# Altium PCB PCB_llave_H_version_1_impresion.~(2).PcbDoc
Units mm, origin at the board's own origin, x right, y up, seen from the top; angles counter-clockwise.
Board outline 85.85 x 71.63 mm, 2 copper layers (Top Layer, Bottom Layer); 116 components, 33 nets, 344 pads, 10 vias.
Unrouted connection lines stored in the file: 18.
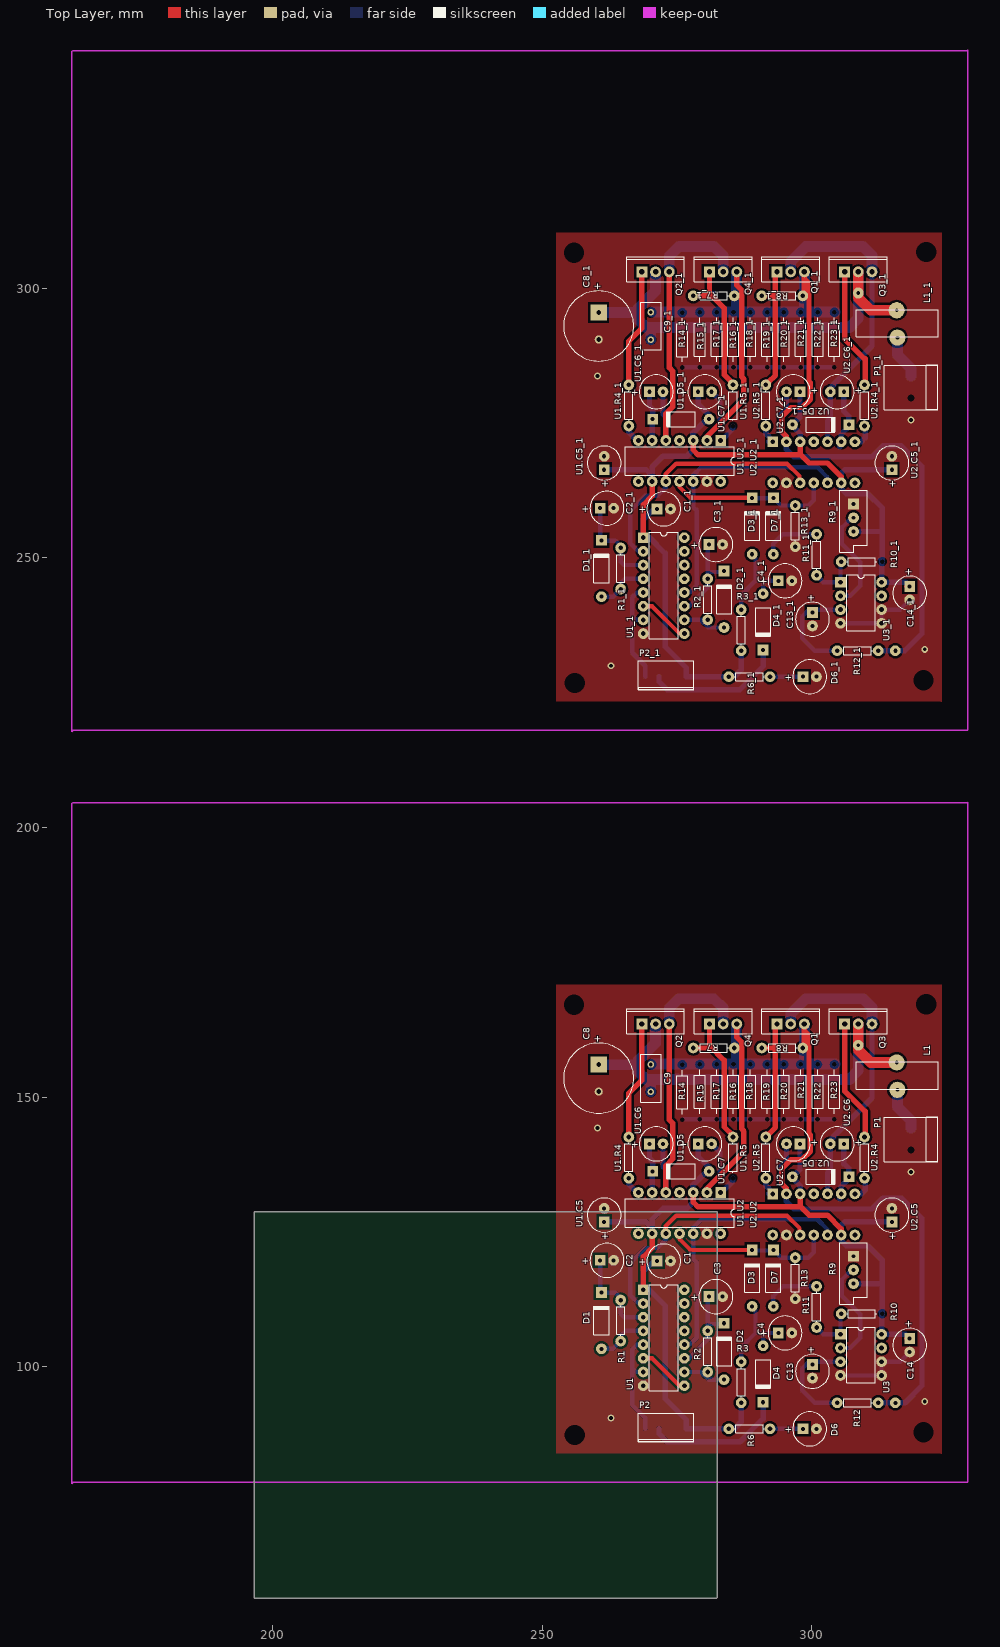
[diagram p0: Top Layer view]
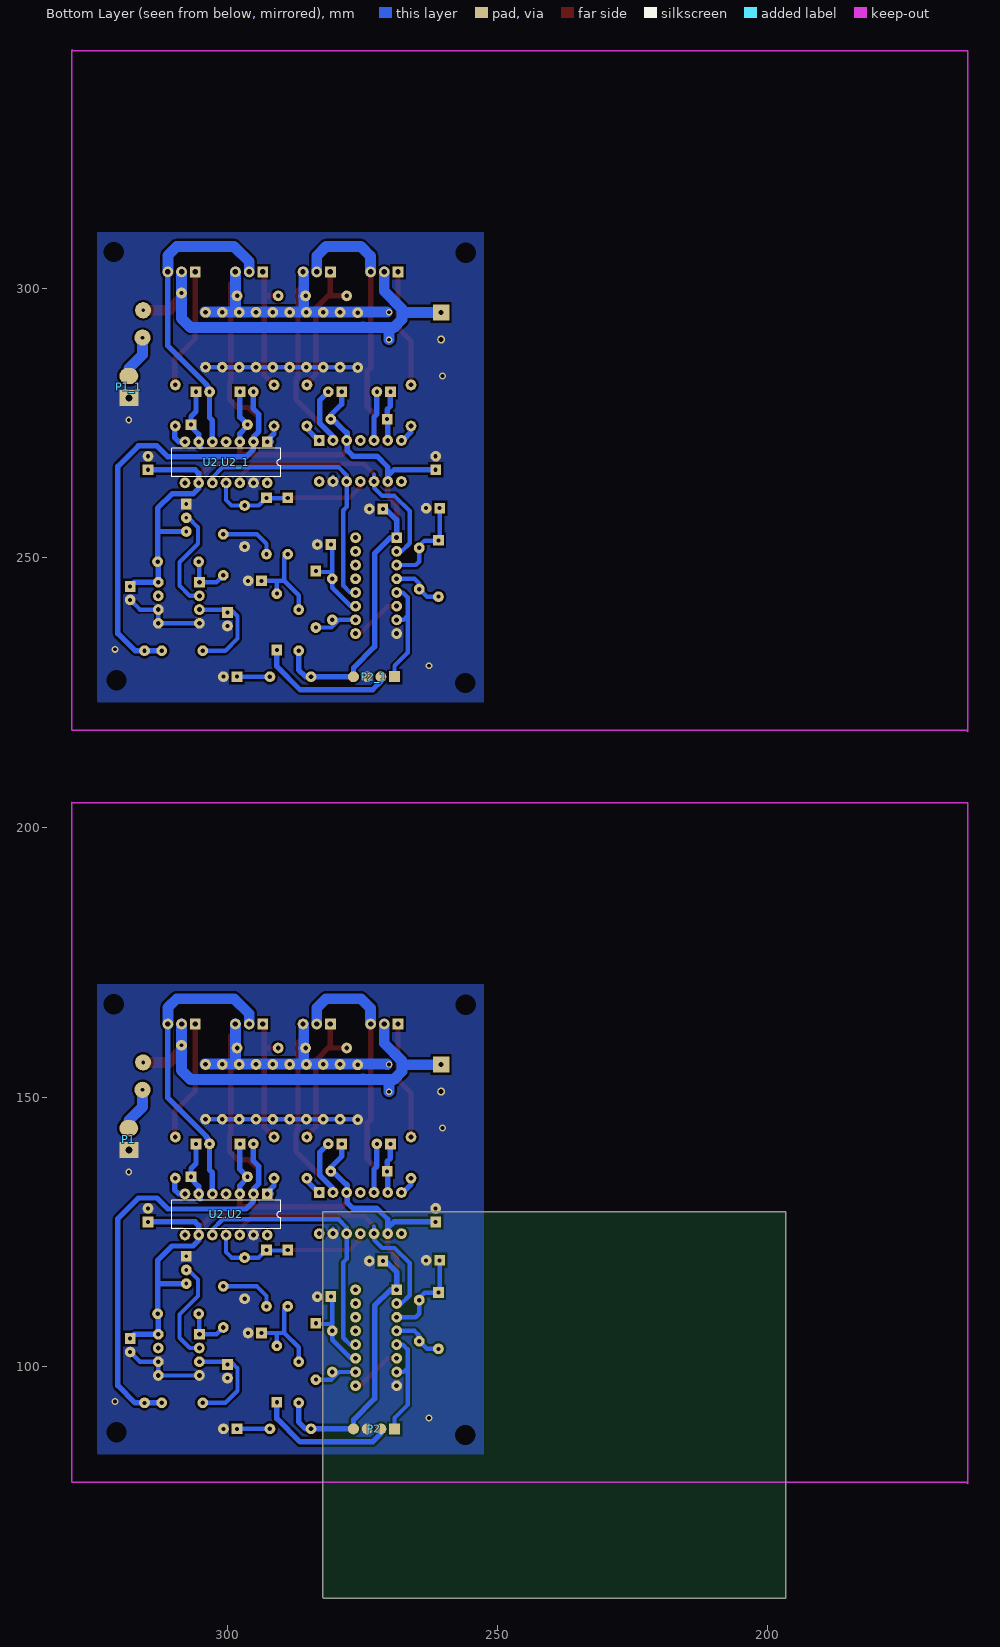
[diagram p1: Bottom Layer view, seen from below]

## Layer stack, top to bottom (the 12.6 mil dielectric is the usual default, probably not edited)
Top Layer: signal copper 0.0356
Dielectric: dielectric 0.32, FR-4, Dk 4.8
Bottom Layer: signal copper 0.0356

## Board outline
196.596,128.778 282.448,128.778 282.448,57.277 282.321,57.15 196.596,57.15

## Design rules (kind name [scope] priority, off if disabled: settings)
Clearance [All] p1: gap=0.4
ComponentClearance [All] p1: gap=0.254 collisioncheckmode=2 verticalgap=0.254
PlaneConnect [All] p1: planeconnectstyle=Direct reliefexpansion=0.508 reliefentries=4 reliefconductorwidth=0.254 reliefairgap=0.254
PolygonConnect [All] p1: connectstyle=Direct reliefconductorwidth=0.254 reliefentries=4 polygonreliefangle="90 Angle"
RoomDefinition U2_1 [InComponentClass('U2')] p1: confinementstyle=ConfineIn formatcopy=TRUE lockcomponents=FALSE outline 311.404,303.657 311.404,256.032 279.527,256.032 279.527,303.657
RoomDefinition U1_1 [InComponentClass('U1')] p2: confinementstyle=ConfineIn formatcopy=TRUE lockcomponents=FALSE outline 255.397,298.069 255.397,257.556 287.02,257.556 287.02,298.069
RoomDefinition U_Puente_H_1 [InComponentClass('U_Puente_H')] p3: confinementstyle=ConfineIn formatcopy=TRUE lockcomponents=FALSE outline 253.746,309.245 324.104,309.245 324.104,274.447 253.746,274.447
RoomDefinition U_INITShutdown_1 [InComponentClass('U_INITShutdown')] p4: confinementstyle=ConfineIn formatcopy=TRUE lockcomponents=FALSE outline 282.956,225.298 298.704,225.298 298.704,263.144 282.956,263.144
RoomDefinition U_Shutdown_1 [InComponentClass('U_Shutdown')] p5: confinementstyle=ConfineOut formatcopy=TRUE lockcomponents=FALSE outline 285.115,227.838 285.115,229.235 288.417,229.235 288.417,227.838
RoomDefinition Llave_H_esquema_1 [InComponentClass('Llave_H_esquema')] p6: confinementstyle=ConfineIn formatcopy=TRUE lockcomponents=FALSE outline 324.104,223.393 324.104,309.245 252.603,309.245 252.603,223.393
RoomDefinition U_4049_1 [InComponentClass('U_4049')] p7: confinementstyle=ConfineIn formatcopy=TRUE lockcomponents=FALSE outline 287.528,233.172 287.528,267.208 257.048,267.208 257.048,233.172
RoomDefinition U2 [InComponentClass('U2')] p8: confinementstyle=ConfineIn formatcopy=TRUE lockcomponents=FALSE outline 311.404,164.211 311.404,116.586 279.527,116.586 279.527,164.211
RoomDefinition U1 [InComponentClass('U1')] p9: confinementstyle=ConfineIn formatcopy=TRUE lockcomponents=FALSE outline 255.397,158.623 255.397,118.11 287.02,118.11 287.02,158.623
RoomDefinition U_Puente_H [InComponentClass('U_Puente_H')] p10: confinementstyle=ConfineIn formatcopy=TRUE lockcomponents=FALSE outline 253.746,169.799 324.104,169.799 324.104,135.001 253.746,135.001
RoomDefinition U_INITShutdown [InComponentClass('U_INITShutdown')] p11: confinementstyle=ConfineIn formatcopy=TRUE lockcomponents=FALSE outline 282.956,85.852 298.704,85.852 298.704,123.698 282.956,123.698
RoomDefinition U_Shutdown [InComponentClass('U_Shutdown')] p12: confinementstyle=ConfineOut formatcopy=TRUE lockcomponents=FALSE outline 285.115,88.392 285.115,89.789 288.417,89.789 288.417,88.392
RoomDefinition Llave_H_esquema [InComponentClass('Llave_H_esquema')] p13: confinementstyle=ConfineIn formatcopy=TRUE lockcomponents=FALSE outline 324.104,83.947 324.104,169.799 252.603,169.799 252.603,83.947
RoomDefinition U_4049 [InComponentClass('U_4049')] p14: confinementstyle=ConfineIn formatcopy=TRUE lockcomponents=FALSE outline 287.528,93.726 287.528,127.762 257.048,127.762 257.048,93.726
RoutingVias [All] p1: holewidth=0.711 width=1.27 viastyle="Through Hole" minholewidth=0.711 minwidth=1.27 maxholewidth=0.711 maxwidth=1.27
SolderMaskExpansion [All] p1: expansion=0.102
TestPointUsage [All] p1: valid=0 allowmultiple=FALSE
Testpoint [All] p1: side=15 testpointundercomponent=TRUE minsize=1.016 maxsize=2.54 preferedsize=1.524 minholesize=0 maxholesize=1.016 preferedholesize=0.813 testpointgrid=0.025 style=1023 order=0-112345678
Width [All] p1: maxlimit=3 minlimit=0.8 preferedwidth=1
17 further rules are at their usual default settings.

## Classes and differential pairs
component class U2: D5 U2.C5 U2.C6 U2.C7 U2.D5 U2.R4 U2.R5 U2.U2 U_2.D5 U_2_C5 U_2_C6 U_2_C7 U_2_R4 U_2_R5 U_2_U2
component class U1: U1.C5 U1.C6 U1.C7 U1.D5 U1.R4 U1.R5 U1.U2 U_1_C5 U_1_C6 U_1_C7 U_1_D5 U_1_R4 U_1_R5 U_1_U2
component class U_INITShutdown: C4 D3 D4 R3
channel class IR2110: U1 U2
component class U_Shutdown: C13 C14 D7 R9 R10 R11 R12 R13 R14 R15 R16 R17 R18 R19 R20 R21 R22 R23 U3
component class U_Puente_H: C8 C9 L1 Q1 Q2 Q3 Q4 R7 R8
component class U_4049: C1 C2 C3 D1 D2 R1 R2 U1
component class Llave_H_esquema: D6 P1 P2 R6

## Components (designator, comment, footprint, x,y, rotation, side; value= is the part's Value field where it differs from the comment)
C1 "Cap Pol1 0.1u" CAPPR2.5-6.3X5 272.542,119.634 r0 top
C1_1 "Cap Pol1 0.1u" CAPPR2.5-6.3X5 272.542,259.08 r0 top (schematic designator C1)
C2 "Cap Pol1" CAPPR2.5-6.3X5 262.001,119.761 r0 top
C2_1 "Cap Pol1" CAPPR2.5-6.3X5 262.001,259.207 r0 top (schematic designator C2)
C3 "Cap Pol1" CAPPR2.5-6.3X5 282.194,113.03 r0 top
C3_1 "Cap Pol1" CAPPR2.5-6.3X5 282.194,252.476 r0 top (schematic designator C3)
C4 "Cap Pol1 4.7u" CAPPR2.5-6.3X5 295.021,106.299 r0 top
C4_1 "Cap Pol1 4.7u" CAPPR2.5-6.3X5 295.021,245.745 r0 top (schematic designator C4)
C8 "Cap Pol1" CAPPR5-13X16 260.477,153.543 r270 top
C8_1 "Cap Pol1" CAPPR5-13X16 260.477,292.989 r270 top (schematic designator C8)
C9 "Cap" RAD-0.2 270.129,153.543 r270 top
C9_1 "Cap" RAD-0.2 270.129,292.989 r270 top (schematic designator C9)
C13 "Cap Pol1 4.7u" CAPPR2.5-6.3X5 300.101,99.187 r270 top
C13_1 "Cap Pol1 4.7u" CAPPR2.5-6.3X5 300.101,238.633 r270 top (schematic designator C13)
C14 "Cap Pol1 0.1u" CAPPR2.5-6.3X5 318.135,104.013 r270 top
C14_1 "Cap Pol1 0.1u" CAPPR2.5-6.3X5 318.135,243.459 r270 top (schematic designator C14)
D1 "Diode1" DO-204AL 260.985,108.585 r90 top
D1_1 "Diode1" DO-204AL 260.985,248.031 r90 top (schematic designator D1)
D2 "Diode1" DO-204AL 283.718,102.87 r90 top
D2_1 "Diode1" DO-204AL 283.718,242.316 r90 top (schematic designator D2)
D3 "Diode1" DO-204AL 288.925,116.459 r90 top
D3_1 "Diode1" DO-204AL 288.925,255.905 r90 top (schematic designator D3)
D4 "Diode1" DO-204AL 290.957,98.679 r270 top
D4_1 "Diode1" DO-204AL 290.957,238.125 r270 top (schematic designator D4)
D6 "LED0" CAPPR2.5-6.3X5 299.593,88.519 r0 top
D6_1 "LED0" CAPPR2.5-6.3X5 299.593,227.965 r0 top (schematic designator D6)
D7 "Diode1" DO-204AL 292.862,116.459 r90 top
D7_1 "Diode1" DO-204AL 292.862,255.905 r90 top (schematic designator D7)
L1 "Inductor" bobina_Choque 313.309,151.511 r0 top
L1_1 "Inductor" bobina_Choque 313.309,290.957 r0 top (schematic designator L1)
P1 "Header 2" pwheader1x2 318.389,142.367 r90 top
P1_1 "Header 2" pwheader1x2 318.389,281.813 r90 top (schematic designator P1)
P2 "Header 4" HDR1X5 276.733,80.899 r0 top
P2_1 "Header 4" HDR1X5 276.733,220.345 r0 top (schematic designator P2)
Q1 "IRF3205" TO-220AB 308.61,163.576 r0 top
Q1_1 "IRF3205" TO-220AB 308.61,303.022 r0 top (schematic designator Q1)
Q2 "IRF3205" TO-220AB 271.018,163.576 r0 top
Q2_1 "IRF3205" TO-220AB 271.018,303.022 r0 top (schematic designator Q2)
Q3 "IRF3205" TO-220AB 296.079,163.576 r0 top
Q3_1 "IRF3205" TO-220AB 296.079,303.022 r0 top (schematic designator Q3)
Q4 "IRF3205" TO-220AB 283.549,163.576 r0 top
Q4_1 "IRF3205" TO-220AB 283.549,303.022 r0 top (schematic designator Q4)
R1 "18k" AXIAL-0.3#1 264.541,108.585 r270 top
R1_1 "18k" AXIAL-0.3#1 264.541,248.031 r270 top (schematic designator R1)
R2 "18k" AXIAL-0.3#1 280.67,102.87 r90 top
R2_1 "18k" AXIAL-0.3#1 280.67,242.316 r90 top (schematic designator R2)
R3 "4.7k" AXIAL-0.3#1 286.893,97.155 r270 top
R3_1 "4.7k" AXIAL-0.3#1 286.893,236.601 r270 top (schematic designator R3)
R6 "1.2k" AXIAL-0.3#1 288.417,88.519 r180 top
R6_1 "1.2k" AXIAL-0.3#1 288.417,227.965 r180 top (schematic designator R6)
R7 "6.8" AXIAL-0.3#1 281.813,159.131 r180 top
R7_1 "6.8" AXIAL-0.3#1 281.813,298.577 r180 top (schematic designator R7)
R8 "6.8" AXIAL-0.3#2 294.513,159.131 r180 top
R8_1 "6.8" AXIAL-0.3#2 294.513,298.577 r180 top (schematic designator R8)
R9 "RPot" VR5 307.721,117.983 r270 top
R9_1 "RPot" VR5 307.721,257.429 r270 top (schematic designator R9)
R10 "3.3k" AXIAL-0.3#3 309.245,109.855 r0 top
R10_1 "3.3k" AXIAL-0.3#3 309.245,249.301 r0 top (schematic designator R10)
R11 "470" AXIAL-0.3#1 300.863,111.125 r90 top
R11_1 "470" AXIAL-0.3#1 300.863,250.571 r90 top (schematic designator R11)
R12 "6.8" AXIAL-0.3#1 308.483,93.345 r180 top locked
R12_1 "6.8" AXIAL-0.3#1 308.483,232.791 r180 top locked (schematic designator R12)
R13 "10k" AXIAL-0.3#1 296.926,116.459 r90 top
R13_1 "10k" AXIAL-0.3#1 296.926,255.905 r90 top (schematic designator R13)
R14 "Res2" AXIAL-0.4#1 275.971,150.936 r90 top
R14_1 "Res2" AXIAL-0.4#1 275.971,290.382 r90 top (schematic designator R14)
R15 "Res2" AXIAL-0.4#1 279.227,151.003 r90 top
R15_1 "Res2" AXIAL-0.4#1 279.227,290.449 r90 top (schematic designator R15)
R16 "Res2" AXIAL-0.4#1 282.344,151.003 r90 top
R16_1 "Res2" AXIAL-0.4#1 282.344,290.449 r90 top (schematic designator R16)
R17 "Res2" AXIAL-0.4#1 285.462,151.003 r90 top
R17_1 "Res2" AXIAL-0.4#1 285.462,290.449 r90 top (schematic designator R17)
R18 "Res2" AXIAL-0.4#1 288.579,151.003 r90 top
R18_1 "Res2" AXIAL-0.4#1 288.579,290.449 r90 top (schematic designator R18)
R19 "Res2" AXIAL-0.4#1 291.696,151.003 r90 top
R19_1 "Res2" AXIAL-0.4#1 291.696,290.449 r90 top (schematic designator R19)
R20 "Res2" AXIAL-0.4#2 294.813,151.003 r90 top
R20_1 "Res2" AXIAL-0.4#2 294.813,290.449 r90 top (schematic designator R20)
R21 "Res2" AXIAL-0.4#2 297.931,151.003 r90 top
R21_1 "Res2" AXIAL-0.4#2 297.931,290.449 r90 top (schematic designator R21)
R22 "Res2" AXIAL-0.4#2 301.048,151.003 r90 top
R22_1 "Res2" AXIAL-0.4#2 301.048,290.449 r90 top (schematic designator R22)
R23 "Res2" AXIAL-0.4#2 304.165,151.003 r90 top
R23_1 "Res2" AXIAL-0.4#2 304.165,290.449 r90 top (schematic designator R23)
U1 "MC54HC4049J" 620-09 272.542,105.41 r270 top
U1.C5 "Cap Pol1 4.7u" CAPPR2.5-6.3X5 261.493,128.143 r90 top (schematic designator C5)
U1.C5_1 "Cap Pol1 4.7u" CAPPR2.5-6.3X5 261.493,267.589 r90 top (schematic designator C5)
U1.C6 "Cap Pol1" CAPPR2.5-6.3X5 271.145,141.351 r0 top (schematic designator C6)
U1.C6_1 "Cap Pol1" CAPPR2.5-6.3X5 271.145,280.797 r0 top (schematic designator C6)
U1.C7 "Cap Pol1" CAPPR2.5-6.3X5 280.162,141.351 r0 top (schematic designator C7)
U1.C7_1 "Cap Pol1" CAPPR2.5-6.3X5 280.162,280.797 r0 top (schematic designator C7)
U1.D5 "Diode" DO-204AL 275.717,136.271 r180 top (schematic designator D5)
U1.D5_1 "Diode" DO-204AL 275.717,275.717 r180 top (schematic designator D5)
U1.R4 "10" AXIAL-0.3#1 266.065,138.811 r90 top (schematic designator R4)
U1.R4_1 "10" AXIAL-0.3#1 266.065,278.257 r90 top (schematic designator R4)
U1.R5 "10" AXIAL-0.3#4 285.369,138.811 r90 top (schematic designator R5)
U1.R5_1 "10" AXIAL-0.3#4 285.369,278.257 r90 top (schematic designator R5)
U1.U2 "IR2110" PDIP14 275.463,128.524 r180 top (schematic designator U2)
U1.U2_1 "IR2110" PDIP14 275.463,267.97 r180 top (schematic designator U2)
U1_1 "MC54HC4049J" 620-09 272.542,244.856 r270 top (schematic designator U1)
U2.C5 "Cap Pol1 4.7u" CAPPR2.5-6.3X5 314.833,128.143 r90 top (schematic designator C5)
U2.C5_1 "Cap Pol1 4.7u" CAPPR2.5-6.3X5 314.833,267.589 r90 top (schematic designator C5)
U2.C6 "Cap Pol1" CAPPR2.5-6.3X5 304.673,141.351 r180 top (schematic designator C6)
U2.C6_1 "Cap Pol1" CAPPR2.5-6.3X5 304.673,280.797 r180 top (schematic designator C6)
U2.C7 "Cap Pol1" CAPPR2.5-6.3X5 296.545,141.351 r180 top (schematic designator C7)
U2.C7_1 "Cap Pol1" CAPPR2.5-6.3X5 296.545,280.797 r180 top (schematic designator C7)
U2.D5 "Diode" DO-204AL 301.625,135.255 r0 top (schematic designator D5)
U2.D5_1 "Diode" DO-204AL 301.625,274.701 r0 top (schematic designator D5)
U2.R4 "10" AXIAL-0.3#1 309.753,138.811 r90 top (schematic designator R4)
U2.R4_1 "10" AXIAL-0.3#1 309.753,278.257 r90 top (schematic designator R4)
U2.R5 "10" AXIAL-0.3#1 291.465,138.811 r90 top (schematic designator R5)
U2.R5_1 "10" AXIAL-0.3#1 291.465,278.257 r90 top (schematic designator R5)
U2.U2 "IR2110" PDIP14 300.355,128.27 r0 bottom (schematic designator U2)
U2.U2_1 "IR2110" PDIP14 300.355,267.716 r0 bottom (schematic designator U2)
U3 "LM393N" 626-05 309.118,102.235 r270 top
U3_1 "LM393N" 626-05 309.118,241.681 r270 top (schematic designator U3)

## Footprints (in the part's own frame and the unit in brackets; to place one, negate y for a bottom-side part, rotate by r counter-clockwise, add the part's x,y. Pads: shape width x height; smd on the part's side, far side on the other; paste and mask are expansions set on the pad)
620-09 [mm] "DIP; 16 Leads; Row Spacing 7.62 mm; Pitch 2.54 mm"
  rect 2x2 hole 0.9: 1(-8.89,-3.81)
  round 2 hole 0.9: 2(-6.35,-3.81) 3(-3.81,-3.81) 4(-1.27,-3.81) 5(1.27,-3.81) 6(3.81,-3.81) 7(6.35,-3.81) 8(8.89,-3.81) 9(8.89,3.81) 10(6.35,3.81) 11(3.81,3.81) 12(1.27,3.81) 13(-1.27,3.81) 14(-3.81,3.81) 15(-6.35,3.81) 16(-8.89,3.81)
  silkscreen extent -9.85,-2.65 9.85,2.65
626-05 [mm] "DIP; 8 Leads; Row Spacing 7.62 mm; Pitch 2.54 mm"
  rect 2x2 hole 0.9: 1(-3.81,-3.81)
  round 2 hole 0.9: 2(-1.27,-3.81) 3(1.27,-3.81) 4(3.81,-3.81) 5(3.81,3.81) 6(1.27,3.81) 7(-1.27,3.81) 8(-3.81,3.81)
  silkscreen extent -5.15,-2.65 5.15,2.65
AXIAL-0.3#1 [mm] "Resistor; 2 Leads"
  round 2 hole 0.85: 1(-3.81,0) 2(3.81,0)
  silkscreen extent -2.77,-0.76 2.77,0.76
AXIAL-0.3#2 [mm] "Resistor; 2 Leads"
  round 2 hole 0.85 paste+0 mask+0.102: 1(-3.81,0)
  round 2 hole 0.85: 2(3.81,0)
  silkscreen extent -2.77,-0.76 2.77,0.76
AXIAL-0.3#3 [mm] "Resistor; 2 Leads"
  round 2 hole 0.85: 1(-3.81,0)
  round 0 / inner round 0 / far side round 2 hole 0.85: 2(3.81,0)
  silkscreen extent -2.77,-0.76 2.77,0.76
AXIAL-0.3#4 [mm] "Resistor; 2 Leads"
  round 0 / inner round 0 / far side round 2 hole 0.85: 1(-3.81,0)
  round 2 hole 0.85: 2(3.81,0)
  silkscreen extent -2.77,-0.76 2.77,0.76
AXIAL-0.4#1 [mm] "Resistor; 2 Leads"
  round 0 / inner round 0 / far side round 2 hole 0.85: 1(-5.08,0) 2(5.08,0)
  silkscreen extent -4.06,-1.02 4.06,1.02
AXIAL-0.4#2 [mm] "Resistor; 2 Leads"
  round 0 / inner round 0 / far side round 2 hole 0.85: 1(-5.08,0)
  round 0 / inner round 0 / far side round 2 hole 0.85 unplated: 2(5.08,0)
  silkscreen extent -4.06,-1.02 4.06,1.02
bobina_Choque [mm]
  round 3 hole 0.7: 1(2.54,-0.127) 2(2.413,4.953)
  silkscreen extent -5.08,0 10.16,5.08
CAPPR2.5-6.3X5 [mm] "Capacitor, Electrolytic, Radial; Body 6.3 x 5 mm (Dia.xH typ); Pin Spacing 2.5 mm (typ)"
  rect 2x2 hole 0.75: 1(-1.25,0)
  round 2 hole 0.75: 2(1.25,0)
  silkscreen extent -3.15,-3.15 3.15,3.15
CAPPR5-13X16 [mm] "Capacitor, Electrolytic, Radial; Body 13 x 16 mm (Dia.xH typ); Pin Spacing 5 mm (typ)"
  rect 3x3 hole 0.9: 1(-2.5,0)
  round 1.5 hole 0.9: 2(2.5,0)
  silkscreen extent -6.5,-6.5 6.5,6.5
DO-204AL [mm] "Diode, Axial; Body 5.2 x 2.7 mm (LxDia. max), Lead Dia. 0.86 mm (max)"
  round 2 hole 0.75: 1(-5.23,0)
  rect 2x2 hole 0.75: 2(5.23,0)
  silkscreen extent -2.65,-1.4 2.75,1.4
HDR1X5 [mil]
  rect 80x80 smd far side: 1(-300,300)
  round 80 smd far side: 2(-200,300) 3(-100,300) 4(0,300)
  silkscreen extent -350,205 55,415
PDIP14 [mm] "DIP; 14 Leads; Row Spacing 7.62 mm; Pitch 2.54 mm"
  rect 2x2 hole 0.9: 1(-7.62,-3.81)
  round 2 hole 0.9: 2(-5.08,-3.81) 3(-2.54,-3.81) 4(0,-3.81) 5(2.54,-3.81) 6(5.08,-3.81) 7(7.62,-3.81) 8(7.62,3.81) 9(5.08,3.81) 10(2.54,3.81) 11(0,3.81) 12(-2.54,3.81) 13(-5.08,3.81) 14(-7.62,3.81)
  silkscreen extent -10.1,-2.65 10.1,2.65
pwheader1x2 [mm]
  round 0 / inner round 0 / far side rect 3x3.5 hole 1.3: 1(-2.159,0)
  oval 3x3.5 smd far side: 2(1.905,0)
  silkscreen extent -4.32,-4.95 3.94,4.95
RAD-0.2 [mm] "Jumper Wire; 2 Leads"
  round 1.2 hole 0.7: 1(-2.54,0) 2(2.54,0)
  silkscreen extent -4.44,-1.91 4.44,1.91
TO-220AB [mm] "TO, Thru-Hole, Vertical, Heatsink Mounted; 3 In-Line Leads; Pitch 2.54 mm"
  rect 2x2 hole 1: 1(-2.54,0)
  round 2 hole 1: 2(0,0) 3(2.54,0)
  silkscreen extent -5.35,-1.85 5.35,2.85
VR5 [mm] "Potentiometer; 3 Leads"
  rect 2x2 hole 0.7: 1(-2.54,0)
  round 2 hole 0.7: 2(2.54,0) 3(0,0)
  silkscreen extent -5.08,-2.54 6.35,2.54

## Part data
C1 C1_1 C4 C4_1 C14 C14_1 U1.C5 U1.C5_1 U2.C5 U2.C5_1: library part "Cap Pol1", "Polarized Capacitor (Radial)"
C2 C2_1 C3 C3_1 C8 C8_1 U1.C6 U1.C6_1 U1.C7 U1.C7_1 U2.C6 U2.C6_1 U2.C7 U2.C7_1: "Polarized Capacitor (Radial)"
C9 C9_1: "Capacitor"
C13 C13_1: library part "Cap Pol1", "Polarized 16V"
D1 D1_1 D2 D2_1: library part Diode, "1N4148"
D3 D3_1 D4 D4_1 D7 D7_1: library part Diode, "1n4148"
D6 D6_1: "Typical INFRARED GaAs LED"
P1 P1_1: "Header, 2-Pin"
P2 P2_1: "Header, 4-Pin"
Q1 Q1_1 Q2 Q2_1 Q3 Q3_1 Q4 Q4_1: "HEXFET Power MOSFET"
R1 R1_1 R2 R2_1 R3 R3_1 R6 R6_1 R7 R7_1 R8 R8_1 U1.R4 U1.R4_1 U1.R5 U1.R5_1 U2.R4 U2.R4_1 U2.R5 U2.R5_1: library part Res2, "Resistor"
R9 R9_1: "Potenciomentro multivuelta"
R10 R10_1 R11 R11_1 R12 R12_1 R13 R13_1: library part Res2, "metal film 1/2 W"
R14 R14_1 R15 R15_1 R16 R16_1 R17 R17_1 R18 R18_1 R19 R19_1 R20 R20_1 R21 R21_1 R22 R22_1 R23 R23_1: "metal film 1W"
U1 U1_1: "Hex Inverting Buffer/Logic-Level Down Converter"
U1.D5 U1.D5_1 U2.D5 U2.D5_1: "1N5819"
U1.U2 U1.U2_1 U2.U2 U2.U2_1: "High and Low Side Driver"
U3 U3_1: "Dual Comparator"

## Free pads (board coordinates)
  round 1.524 hole 3.75: 0(255.905,167.132) 0(255.905,306.578) 0(256.032,87.376) 0(256.032,226.822) 0(320.675,87.884) 0(320.675,227.33) 0(321.183,167.259) 0(321.183,306.705)
  round 2 hole 0.762: 1(315.468,93.345) 1(315.468,232.791)

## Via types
v1: diameter 1.27, hole 0.711, Top Layer to Bottom Layer, 8 vias
v2: diameter 2, hole 0.711, Top Layer to Bottom Layer, 2 vias

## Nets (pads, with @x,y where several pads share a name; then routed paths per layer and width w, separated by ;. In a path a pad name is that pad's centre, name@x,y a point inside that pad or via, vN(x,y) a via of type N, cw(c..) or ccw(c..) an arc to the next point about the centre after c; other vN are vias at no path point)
COMMON: C9.1 pad.1@315.468,93.345 Q3.3 Q4.3 R7.1 R8.1 R12.1 R14.2 R15.2 R16.2 R17.2 R18.2 R19.2 R20.2 R21.2 R22.2 R23.2 U1.C7.2 U1.U2.2 U2.C7.2 U2.U2.2 | length 217.5
  Top Layer w1: U1.U2.2 280.543,133.096 287.401,139.954 287.401,143.637 287.274,143.764 287.274,143.891 287.02,144.145 287.02,160.147 286.089,161.078 Q4.3 ; U2.U2.2 295.275,133.096 294.386,133.985 294.386,136.652 296.164,138.43 298.196,138.43 299.72,139.954 299.72,142.997 299.466,143.251 299.466,161.417 298.619,162.264 ; R8.1@298.619,159.131 Q3.3
  Bottom Layer w1: U1.U2.2 280.543,133.096 282.956,135.509 282.956,139.807 U1.C7.2 ; R7.1@286.004,159.064 286.089,159.149 Q4.3 ; U2.C7.2 295.295,138.196 294.279,137.18 294.279,133.98 295.275,132.984 295.275,130.683 296.672,129.286 311.15,129.286 313.182,131.318 316.611,131.318 320.421,127.508 320.421,96.52 317.246,93.345 R12.1
  Bottom Layer w2: C9.1@270.475,156.083 270.536,156.143 R23.2@304.292,156.143 ; R17.2@285.97,156.143 Q4.3@285.97,163.542 ; R7.1@285.97,159.131 R7.1@286.036,159.064 ; R21.2@298.619,156.143 Q3.3
GND: C1.2 C2.2 C3.2 C4.2 C8.2 C13.2 C14.2 D6.2 P1.1 P2.3 pad.0@255.905,167.132 pad.0@256.032,87.376 pad.0@320.675,87.884 pad.0@321.183,167.259 R9.1 R13.1 R14.1 R15.1 R16.1 R17.1 R18.1 R19.1 R20.1 R21.1 R22.1 R23.1 U1.8 U1.C5.2 U1.U2.13 U2.C5.2 U2.U2.13 U3.4 U3.5 U3.6 | length 45.2
  Top Layer w0.8: U3.5@312.888,98.425 312.908,98.445 U3.5 ; U3.6@312.908,100.945 U3.6
  Bottom Layer w0.8: R14.1@276.038,145.923 R23.1 ; U1.U2.13 U1.U2.13@280.543,125.603 ; U3.4 U3.5 ; U3.5@312.908,98.445 U3.6@312.908,100.945 ; U3.6 316.337,100.965 C14.2
  other v1: 262.763,90.551 320.929,93.599 318.389,136.144 260.223,144.272
HO1: Q2.1 U1.R4.2 | length 22
  Top Layer w1: U1.R4.2 266.065,150.749 268.478,153.162 Q2.1
HO2: Q1.1 U2.R4.2 | length 22
  Top Layer w1: Q1.1 306.07,151.13 309.88,147.32 ; U2.R4.2@309.88,143.256 309.88,147.447
IN_SD: D4.2 P2.2 | length 25.6
  Bottom Layer w1: P2.2 271.653,87.63 273.177,86.106 286.639,86.106 290.957,90.424 D4.2
LO1: Q4.1 R7.2 U1.R5.2 | length 26.4
  Top Layer w1: R7.2@277.749,159.131 281.409,159.131 281.421,159.142 ; Q4.1 281.009,159.554 283.718,156.845 283.718,144.526 285.369,142.875 U1.R5.2
LO2: Q3.1 R8.2 U2.R5.2 | length 24.5
  Top Layer w1: R8.2@290.322,158.877 R8.2@290.576,159.131 ; R8.2 293.243,159.131 ; U2.R5.2@291.465,143.129 291.973,143.129 293.243,144.399 293.243,163.28 Q3.1
MOTOR+: Q2.3 Q4.2 U1.C6.2 U1.U2.5 | length 58.6
  Top Layer w1: U1.U2.5 272.923,137.287 274.193,138.557 274.193,145.187 273.558,145.822 Q2.3
  Bottom Layer w1: U1.C6.2 272.395,137.18 272.923,136.652 U1.U2.5
  Bottom Layer w2: Q2.3 273.558,166.497 275.336,168.275 281.813,168.275 283.549,166.539 Q4.2
MOTOR-: Q1.3 Q3.2 U2.C6.2 U2.U2.5 | length 56.8
  Bottom Layer w1: U2.U2.5 302.895,136.017 303.423,136.545 303.423,142.006 304.023,142.606 304.023,142.733 311.15,149.86 Q1.3
  Bottom Layer w2: Q3.2 296.079,165.481 298.873,168.275 309.499,168.275 311.15,166.624 Q1.3
NetC2_1: C2.1 D1.2 R1.1 U1.3 | length 17.4
  Bottom Layer w0.8: C2.1 260.751,114.049 261.046,113.754 263.563,113.754 264.541,112.776 264.541,109.855 265.176,109.22 U1.3
NetC3_1: C3.1 D2.2 R2.2 U1.11 | length 17
  Bottom Layer w0.8: U1.11 277.241,101.6 280.67,105.029 280.67,112.756 C3.1 ; 280.67,107.95 283.568,107.95 D2.2
NetC4_1: C4.1 D3.1 D4.1 R3.1 | length 18.2
  Bottom Layer w0.8: R3.1 286.893,103.632 289.56,106.299 ; D3.1 289.56,110.594 289.56,106.299 ; D4.1 290.957,106.299 ; C4.1 289.56,106.299
NetC13_1: C13.1 R12.2 U3.3 | length 19.1
  Bottom Layer w0.8: R12.2 300.482,93.345 298.236,95.591 298.236,99.735 299.466,100.965 U3.3
NetD1_1: D1.1 R1.2 U1.4 | length 9.7
  Bottom Layer w0.8: D1.1 263.121,103.355 R1.2 264.541,105.791 265.43,106.68 U1.4
NetD2_1: D2.1 R2.1 U1.10 | length 8
  Bottom Layer w0.8: U1.10 279.4,99.06 280.82,97.64 D2.1
NetD6_1: D6.1 R6.1 | length 6.1
  Bottom Layer w0.8: R6.1 D6.1
NetD7_1: D7.1 R11.2 | length 10.7
  Bottom Layer w0.8: D7.1 292.862,113.157 294.64,114.935 R11.2
NetR9_3: R9.3 U3.2 | length 19.6
  Bottom Layer w0.8: U3.2 307.086,103.505 308.991,105.41 308.991,109.728 305.562,113.157 305.562,116.205 307.34,117.983 R9.3
NetR10_1: R10.1 R11.1 U3.1 | length 9.5
  Bottom Layer w0.8: R11.1 302.133,106.045 U3.1 305.308,109.855 R10.1@305.816,110.363
NetU1.C6_1: U1.C6.1 U1.D5.2 U1.U2.6 | length 9.8
  Bottom Layer w1: U1.C6.1 269.895,138.664 270.487,138.072 270.487,135.763 270.383,135.659 U1.U2.6 ; U1.D5.2@270.129,136.294 U1.D5.2@270.487,136.652
NetU1.R4_1: U1.R4.1 U1.U2.7 | length 3.8
  Bottom Layer w1: U1.R4.1@266.065,135.255 266.065,133.858 267.589,132.334 U1.U2.7
NetU1.R5_1: U1.R5.1 U1.U2.1 | length 3.7
  Bottom Layer w1: U1.U2.1 283.21,132.334 285.369,134.493 U1.R5.1
NetU1_6: U1.6 U1.9 | length 9.9
  Top Layer w0.8: U1.6 270.383,101.6 275.463,96.52 U1.9
  Bottom Layer w0.8: U1.9@276.225,96.52 U1.9
NetU2.C6_1: U2.C6.1 U2.D5.2 U2.U2.6 | length 10.8
  Bottom Layer w1: U2.U2.6@305.181,131.191 U2.U2.6@305.181,131.953 ; U2.U2.6 305.435,133.477 U2.D5.2@306.982,135.024 ; U2.C6.1 305.923,137.688 306.855,136.756 U2.D5.2
NetU2.R4_1: U2.R4.1 U2.U2.7 | length 4.9
  Bottom Layer w1: U2.U2.7 309.118,132.08 309.88,132.842 U2.R4.1@309.88,135.509
NetU2.R5_1: U2.R5.1 U2.U2.1 | length 4.7
  Bottom Layer w1: U2.R5.1@291.465,135.509 291.465,133.604 292.735,132.334 U2.U2.1 U2.U2.1@291.973,132.08
PWM: P2.1 U1.5 U1.7 | length 20.5
  Bottom Layer w0.8: 266.7,99.822 267.462,99.06 U1.7 ; U1.5 267.589,104.14 266.7,103.251 266.7,92.964 269.113,90.551 P2.1
SD: D3.2 D7.2 R13.2 U1.U2.11 U2.U2.11 | length 31.1
  Top Layer w0.8: U1.U2.11 275.463,123.698 277.472,121.689 D3.2
  Bottom Layer w0.8: D3.2 289.022,121.592 D7.2@292.959,121.592 ; D7.2 294.282,120.269 299.339,120.269 300.355,121.285 U2.U2.11
U1.HIN: U1.2 U1.U2.10 U2.U2.12 | length 48.9
  Top Layer w0.8: U1.U2.10 272.923,126.111 274.828,128.016 295.402,128.016 297.688,125.73 U2.U2.12@297.688,124.587
  Bottom Layer w0.8: U1.2 267.843,111.76 266.319,113.284 266.319,119.253 269.113,122.047 271.399,122.047 272.923,123.571 272.923,125.984
U1.LIN: U1.12 U1.U2.12 U2.U2.10 | length 50.9
  Bottom Layer w0.8: U1.12 277.368,104.14 278.638,105.41 278.638,119.38 278.003,120.015 278.003,125.857 279.527,127.381 300.99,127.381 302.895,125.476 U2.U2.10
VCC_MOTOR: L1.1 P1.2 | length 8.2
  Bottom Layer w2: L1.1 315.849,148.209 318.389,145.669 P1.2
VCC_MOTOR_FILTRADO: C8.1 C9.2 L1.2 Q1.2 Q2.2 | length 83.3
  Top Layer w2: Q1.2 308.61,158.75 310.896,156.464 L1.2
  Bottom Layer w2: C8.1 267.422,156.043 ; C9.2 270.129,153.162 270.256,153.289 ; Q2.2 271.018,160.02 267.716,156.718 267.716,154.813 269.24,153.289 306.959,153.289 308.61,154.94 Q1.2 ; 274.955,153.416 275.082,153.289
  other v2: 308.61,159.639
VDD: C1.1 C14.1 P2.4 R3.2 R6.2 R9.2 R10.2 U1.1 U1.C5.1 U1.C7.1 U1.D5.1 U1.U2.3 U1.U2.9 U2.C5.1 U2.C7.1 U2.D5.1 U2.U2.3 U2.U2.9 U3.8 | length 188.7
  Top Layer w0.8: U3.8@312.674,105.918 312.801,106.045 U3.8 ; C14.1@317.52,105.263 C14.1
  Top Layer w1: U1.1 268.732,120.396 270.383,122.047 U1.U2.9 ; U1.U2.3 278.003,130.556 278.892,129.667 297.942,129.667 ; U2.U2.3 297.815,129.794 299.466,128.143 302.895,128.143 305.435,125.603 U2.U2.9
  Bottom Layer w0.8: C1.1@270.891,119.634 C1.1 ; R10.2@312.692,110.345 R10.2@312.709,110.363
  Bottom Layer w1: U1.C5.1 269.22,126.893 270.383,125.73 ; U1.U2.9 270.383,127.381 272.415,129.413 276.86,129.413 277.876,130.429 277.876,133.731 278.13,133.985 ; C1.1 270.764,119.634 268.732,117.602 U1.1 269.875,114.3 272.796,111.379 272.796,94.107 276.733,90.17 P2.4 285.623,88.519 286.893,89.789 R3.2 ; 278.003,133.731 280.035,135.763 U1.D5.1@280.947,135.763 ; U1.C7.1 278.912,139.045 280.947,137.01 U1.D5.1 ; U2.D5.1 296.418,135.255 297.795,136.632 U2.C7.1 ; U2.D5.1@296.522,134.897 297.815,133.604 U2.U2.3 ; R9.2 313.055,115.443 ; R10.2@312.928,110.109 U3.8 317.353,106.045 C14.1 ; R10.2 313.055,119.761 310.388,122.428 306.451,122.428 305.435,123.444 305.435,126.238 306.09,126.893 U2.C5.1
pads on no net: C1_1.1 C1_1.2 C2_1.1 C2_1.2 C3_1.1 C3_1.2 C4_1.1 C4_1.2 C8_1.1 C8_1.2 C9_1.1 C9_1.2 C13_1.1 C13_1.2 C14_1.1 C14_1.2 D1_1.1 D1_1.2 D2_1.1 D2_1.2 D3_1.1 D3_1.2 D4_1.1 D4_1.2 D6_1.1 D6_1.2 D7_1.1 D7_1.2 L1_1.1 L1_1.2 P1_1.1 P1_1.2 P2_1.1 P2_1.2 P2_1.3 P2_1.4 Q1_1.1 Q1_1.2 Q1_1.3 Q2_1.1 Q2_1.2 Q2_1.3 Q3_1.1 Q3_1.2 Q3_1.3 Q4_1.1 Q4_1.2 Q4_1.3 R1_1.1 R1_1.2 R2_1.1 R2_1.2 R3_1.1 R3_1.2 R6_1.1 R6_1.2 R7_1.1 R7_1.2 R8_1.1 R8_1.2 R9_1.1 R9_1.2 R9_1.3 R10_1.1 R10_1.2 R11_1.1 R11_1.2 R12_1.1 R12_1.2 R13_1.1 R13_1.2 R14_1.1 R14_1.2 R15_1.1 R15_1.2 R16_1.1 R16_1.2 R17_1.1 R17_1.2 R18_1.1 R18_1.2 R19_1.1 R19_1.2 R20_1.1 R20_1.2 R21_1.1 R21_1.2 R22_1.1 R22_1.2 R23_1.1 R23_1.2 U1.13 U1.14 U1.15 U1.16 U1.C5_1.1 U1.C5_1.2 U1.C6_1.1 U1.C6_1.2 U1.C7_1.1 U1.C7_1.2 U1.D5_1.1 U1.D5_1.2 U1.R4_1.1 U1.R4_1.2 U1.R5_1.1 U1.R5_1.2 U1.U2.4 U1.U2.8 U1.U2.14 U1.U2_1.1 U1.U2_1.2 U1.U2_1.3 U1.U2_1.4 U1.U2_1.5 U1.U2_1.6 U1.U2_1.7 U1.U2_1.8 U1.U2_1.9 U1.U2_1.10 U1.U2_1.11 U1.U2_1.12 U1.U2_1.13 U1.U2_1.14 U1_1.1 U1_1.2 U1_1.3 U1_1.4 U1_1.5 U1_1.6 U1_1.7 U1_1.8 U1_1.9 U1_1.10 U1_1.11 U1_1.12 U1_1.13 U1_1.14 U1_1.15 U1_1.16 U2.C5_1.1 U2.C5_1.2 U2.C6_1.1 U2.C6_1.2 U2.C7_1.1 U2.C7_1.2 U2.D5_1.1 U2.D5_1.2 U2.R4_1.1 U2.R4_1.2 U2.R5_1.1 U2.R5_1.2 U2.U2.4 U2.U2.8 U2.U2.14 U2.U2_1.1 U2.U2_1.2 U2.U2_1.3 U2.U2_1.4 U2.U2_1.5 U2.U2_1.6 U2.U2_1.7 U2.U2_1.8 U2.U2_1.9 U2.U2_1.10 U2.U2_1.11 U2.U2_1.12 U2.U2_1.13 U2.U2_1.14 U3.7 U3_1.1 U3_1.2 U3_1.3 U3_1.4 U3_1.5 U3_1.6 U3_1.7 U3_1.8
copper on no net: | length 1112.9
  Top Layer w0.8: 268.732,241.046 270.383,241.046 275.463,235.966 276.352,235.966 ; 272.923,264.16 272.923,265.557 274.828,267.462 295.402,267.462 297.688,265.176 297.688,264.033 ; 275.463,264.16 275.463,263.144 277.472,261.135 288.925,261.135 ; 312.674,245.364 312.801,245.491 312.928,245.491 ; 312.888,237.871 312.908,237.891 312.928,237.871 ; 312.908,240.391 312.928,240.411 ; 317.52,244.709 318.135,244.709
  Top Layer w1: 266.065,282.067 266.065,290.195 268.478,292.608 268.478,303.022 ; 268.732,253.746 268.732,259.842 270.383,261.493 270.383,264.16 ; 272.923,271.78 272.923,276.733 274.193,278.003 274.193,284.633 273.558,285.268 273.558,303.022 ; 277.749,298.577 281.409,298.577 281.421,298.588 ; 278.003,271.78 278.003,270.002 278.892,269.113 297.942,269.113 ; 280.543,271.78 280.543,272.542 287.401,279.4 287.401,283.083 287.274,283.21 287.274,283.337 287.02,283.591 287.02,299.593 286.089,300.524 286.089,303.022 ; 281.009,303.022 281.009,299 283.718,296.291 283.718,283.972 285.369,282.321 285.369,282.067 ; 290.322,298.323 290.576,298.577 ; 290.703,298.577 293.243,298.577 ; 291.465,282.575 291.973,282.575 293.243,283.845 293.243,302.726 293.539,303.022 ; 295.275,271.526 295.275,272.542 294.386,273.431 294.386,276.098 296.164,277.876 298.196,277.876 299.72,279.4 299.72,282.443 299.466,282.697 299.466,300.863 298.619,301.71 ; 297.815,271.526 297.815,269.24 299.466,267.589 302.895,267.589 305.435,265.049 305.435,263.906 ; 298.619,298.577 298.619,303.022 ; 306.07,303.022 306.07,290.576 309.88,286.766 ; 309.88,282.702 309.88,286.893
  Top Layer w2: 308.61,303.022 308.61,298.196 310.896,295.91 315.722,295.91
  Bottom Layer w0.8: 260.751,259.207 260.751,253.495 261.046,253.2 263.563,253.2 264.541,252.222 264.541,249.301 265.176,248.666 268.732,248.666 ; 260.985,242.801 263.121,242.801 264.541,244.221 264.541,245.237 265.43,246.126 268.732,246.126 ; 266.7,239.268 267.462,238.506 268.732,238.506 ; 268.732,243.586 267.589,243.586 266.7,242.697 266.7,232.41 269.113,229.997 269.113,227.965 ; 268.732,251.206 267.843,251.206 266.319,252.73 266.319,258.699 269.113,261.493 271.399,261.493 272.923,263.017 272.923,265.43 ; 270.891,259.08 271.292,259.08 ; 276.038,285.369 304.165,285.369 ; 276.225,235.966 276.352,235.966 ; 276.352,238.506 279.4,238.506 280.82,237.086 283.718,237.086 ; 276.352,241.046 277.241,241.046 280.67,244.475 280.67,252.202 280.944,252.476 ; 276.352,243.586 277.368,243.586 278.638,244.856 278.638,258.826 278.003,259.461 278.003,265.303 279.527,266.827 300.99,266.827 302.895,264.922 302.895,263.906 ; 280.543,264.16 280.543,265.049 ; 280.67,247.396 283.568,247.396 283.718,247.546 ; 286.893,240.411 286.893,243.078 289.56,245.745 ; 288.925,250.675 289.56,250.04 289.56,245.745 ; 288.925,261.135 289.022,261.038 292.959,261.038 ; 290.957,243.355 290.957,245.745 ; 292.227,227.965 298.343,227.965 ; 292.862,250.675 292.862,252.603 294.64,254.381 300.863,254.381 ; 292.862,261.135 294.282,259.715 299.339,259.715 300.355,260.731 300.355,263.906 ; 293.771,245.745 289.56,245.745 ; 300.863,246.761 302.133,245.491 305.308,245.491 305.308,249.301 305.816,249.809 ; 304.673,232.791 300.482,232.791 298.236,235.037 298.236,239.181 299.466,240.411 305.308,240.411 ; 305.308,237.871 312.928,237.871 ; 305.308,242.951 307.086,242.951 308.991,244.856 308.991,249.174 305.562,252.603 305.562,255.651 307.34,257.429 307.721,257.429 ; 312.692,249.791 312.709,249.809 ; 312.908,237.891 312.908,240.391 ; 312.928,240.411 316.337,240.411 318.135,242.209
  Bottom Layer w1: 261.493,266.339 269.22,266.339 270.383,265.176 ; 266.065,274.701 266.065,273.304 267.589,271.78 267.843,271.78 ; 269.895,280.797 269.895,278.11 270.487,277.518 270.487,275.209 270.383,275.105 270.383,271.78 ; 270.129,275.74 270.487,276.098 ; 270.383,264.16 270.383,266.827 272.415,268.859 276.86,268.859 277.876,269.875 277.876,273.177 278.13,273.431 ; 271.292,259.08 270.764,259.08 268.732,257.048 268.732,253.746 269.875,253.746 272.796,250.825 272.796,233.553 276.733,229.616 276.733,227.965 285.623,227.965 286.893,229.235 286.893,232.791 ; 271.653,227.965 271.653,227.076 273.177,225.552 286.639,225.552 290.957,229.87 290.957,232.895 ; 272.395,280.797 272.395,276.626 272.923,276.098 272.923,271.78 ; 278.003,273.177 280.035,275.209 280.947,275.209 ; 278.912,280.797 278.912,278.491 280.947,276.456 280.947,275.717 ; 280.543,271.78 280.543,272.542 282.956,274.955 282.956,279.253 281.412,280.797 ; 283.083,271.78 283.21,271.78 285.369,273.939 285.369,274.447 ; 286.004,298.51 286.089,298.595 286.089,303.022 ; 291.465,274.955 291.465,273.05 292.735,271.78 292.735,271.526 291.973,271.526 ; 295.295,280.797 295.295,277.642 294.279,276.626 294.279,273.426 295.275,272.43 295.275,270.129 296.672,268.732 311.15,268.732 313.182,270.764 316.611,270.764 320.421,266.954 320.421,235.966 317.246,232.791 312.293,232.791 ; 296.395,274.701 296.418,274.701 297.795,276.078 297.795,280.797 ; 296.522,274.343 297.815,273.05 297.815,271.526 ; 302.895,271.526 302.895,275.463 303.423,275.991 303.423,281.452 304.023,282.052 304.023,282.179 311.15,289.306 311.15,303.022 ; 305.181,270.637 305.181,271.399 ; 305.435,271.526 305.435,272.923 306.982,274.47 ; 305.923,280.797 305.923,277.134 306.855,276.202 306.855,274.701 ; 307.721,254.889 313.055,254.889 ; 307.975,271.526 309.118,271.526 309.88,272.288 309.88,274.955 ; 312.928,249.555 312.928,245.491 317.353,245.491 318.135,244.709 ; 313.055,249.301 313.055,259.207 310.388,261.874 306.451,261.874 305.435,262.89 305.435,265.684 306.09,266.339 314.833,266.339
  Bottom Layer w2: 260.477,295.489 267.422,295.489 ; 270.129,290.449 270.129,292.608 270.256,292.735 ; 270.475,295.529 270.536,295.589 304.292,295.589 ; 271.018,303.022 271.018,299.466 267.716,296.164 267.716,294.259 269.24,292.735 306.959,292.735 308.61,294.386 308.61,303.022 ; 273.558,303.022 273.558,305.943 275.336,307.721 281.813,307.721 283.549,305.985 283.549,303.022 ; 274.955,292.862 275.082,292.735 ; 285.97,295.589 285.97,302.988 ; 285.97,298.577 286.036,298.51 ; 296.079,303.022 296.079,304.927 298.873,307.721 309.499,307.721 311.15,306.07 311.15,303.022 ; 298.619,295.589 298.619,303.022 ; 315.849,290.83 315.849,287.655 318.389,285.115 318.389,283.718
  other v1: 262.763,229.997 320.929,233.045 318.389,275.59 260.223,283.718
  other v2: 308.61,299.085

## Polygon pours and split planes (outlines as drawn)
no net on Top Layer "Top Layer-GND" (solid, remove dead copper, pour order 1000): 252.603,223.395 252.603,310.261 324.104,310.261 324.104,223.395 323.977,223.266 323.85,223.395
GND on Top Layer "Top Layer-GND" (solid, remove dead copper, pour order 1000): 252.603,83.949 252.603,170.815 324.104,170.815 324.104,83.949 323.977,83.82 323.85,83.949
no net on Bottom Layer "Bottom Layer-GND" (solid, remove dead copper, pour order 1001): 252.603,223.266 252.603,310.388 324.231,310.388 324.231,223.394 324.104,223.266
GND on Bottom Layer "Bottom Layer-GND" (solid, remove dead copper, pour order 1001): 252.603,83.82 252.603,170.942 324.231,170.942 324.231,83.948 324.104,83.82

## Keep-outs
Keep-Out Layer:
  lines w0.254: 162.814,78.359 163.068,78.613 328.93,78.613 328.93,204.724 328.803,204.597 162.941,204.597 162.814,204.47 162.814,78.359 ; 162.814,217.805 163.068,218.059 328.93,218.059 328.93,344.17 328.803,344.043 162.941,344.043 162.814,343.916 162.814,217.805

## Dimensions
328.803,284.861 to 162.814,234.188 on Top Layer
165.862,217.805 to 170.18,343.789 on Top Layer
328.803,145.415 to 162.814,94.742 on Top Layer
165.862,78.359 to 170.18,204.343 on Top Layer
